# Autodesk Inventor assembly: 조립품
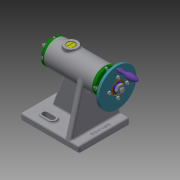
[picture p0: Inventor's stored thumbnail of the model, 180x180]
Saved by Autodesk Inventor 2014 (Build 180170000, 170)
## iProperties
Created: 2019-10
Part Number: 조립품
Document SubType Name: Assembly
Designer: kh
Author: kh
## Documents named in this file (18)
- C:\Users\kh\Desktop\491004V1002\조립품.iam
- C:\Users\kh\Desktop\491004V1002\본체.ipt
- C:\Users\kh\Desktop\491004V1002\공용부품\나사.ipt
- C:\Users\kh\Desktop\491004V1002\공용부품\나사축.ipt
- C:\Users\kh\Desktop\491004V1002\공용부품\너트 M8.ipt
- C:\Users\kh\Desktop\491004V1002\공용부품\돌림판.ipt
- C:\Users\kh\Desktop\491004V1002\공용부품\멈춤나사 M3.ipt
- C:\Users\kh\Desktop\491004V1002\공용부품\볼트 M3.ipt
- C:\Users\kh\Desktop\491004V1002\공용부품\부시.ipt
- C:\Users\kh\Desktop\491004V1002\공용부품\센터.ipt
- C:\Users\kh\Desktop\491004V1002\공용부품\센터홀더.ipt
- C:\Users\kh\Desktop\491004V1002\공용부품\슬리브.ipt
- C:\Users\kh\Desktop\491004V1002\공용부품\와셔.ipt
- C:\Users\kh\Desktop\491004V1002\공용부품\중공축.ipt
- C:\Users\kh\Desktop\491004V1002\공용부품\커버.ipt
- C:\Users\kh\Desktop\491004V1002\공용부품\키 4 x 4 x 10.ipt
- C:\Users\kh\Desktop\491004V1002\공용부품\플랜지.ipt
- C:\Users\kh\Desktop\491004V1002\공용부품\핸들.ipt
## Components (2 placed, 2 different names)
1. 플랜지:1 — Insert:4, Mate:1, Insert:9, Insert:10, Insert:17
2. 핸들:1 — Mate:2, Flush:1, Angle:11
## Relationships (8: Insert 4, Mate 2, Flush 1, Angle 1)
- Insert:4: 플랜지:1
- Mate:1: 플랜지:1
- Insert:9: 플랜지:1
- Insert:10: 플랜지:1
- Mate:2: 핸들:1
- Flush:1: 핸들:1
- Insert:17: 플랜지:1
- Angle:11: 핸들:1
